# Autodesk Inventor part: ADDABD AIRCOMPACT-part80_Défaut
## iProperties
Shininess: 64.0
Length Units: 11269
Angle Units: 11279
Time Units: 11290
Mass Units: 11283
Length Display Precision: 3
Angle Display Precision: 2
Compacted: True
Part Number: ADDABD AIRCOMPACT-part80_Défaut
Document SubType Name: Modeling
Created: 2006-01
Material: Par défaut
Designer: riri
Density: 0.0
Volumn: 0.0
Area: 0.0
PropertySet Name: Model Information
Control State: 0
Master: False
Checked Out: False
Author: riri
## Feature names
1. Base1
2. Extrusion1
